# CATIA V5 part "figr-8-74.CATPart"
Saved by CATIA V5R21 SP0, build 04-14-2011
Part number: Part1
Bounding box of the stored display mesh (mm): x -48 to 48, y -106.879 to 106.685, z -32.702 to 29.91
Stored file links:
  D:\CATIA V5R21 E-RESOURCES\CATIA-V5R21\catia-v5r21-prt\c08-catia-v5r20-prt\c08-catia-v5r21-figr-8-74.CATPart
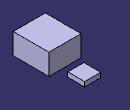
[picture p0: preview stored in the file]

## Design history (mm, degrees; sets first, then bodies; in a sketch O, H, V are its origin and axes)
Body1 (main body)
  Sketch1 on yz-plane, origin (0, 0, 0), H (0, 1, 0), V (0, 0, 1)
    line L1 (-106.8789, 29.9101) -> (0, 29.9101)
    line L2 (0, 29.9101) -> (0, -32.7018)
    line L3 (0, -32.7018) -> (-106.8789, -32.7018)
    line L4 (-106.8789, -32.7018) -> (-106.8789, 29.9101)
    point P3 (0, -32.7018)
    horizontal: L1 H, L3 H
    vertical: L2 V, L4 V
    coincidence: P3 V
  Pad1: profile Sketch1, direction (1, 0, 0), length 48, mirrored extent
  Sketch2 on yz-plane, origin (0, 0, 0), H (0, 1, 0), V (0, 0, 1)
    line L1 (56.3417, 7.481) -> (106.6854, 7.481)
    line L2 (106.6854, 7.481) -> (106.6854, -6.5572)
    line L3 (106.6854, -6.5572) -> (56.3417, -6.5572)
    line L4 (56.3417, -6.5572) -> (56.3417, 7.481)
    horizontal: L1 H, L3 H
    vertical: L2 V, L4 V
  Pad2: profile Sketch2, direction (1, 0, 0), length 48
